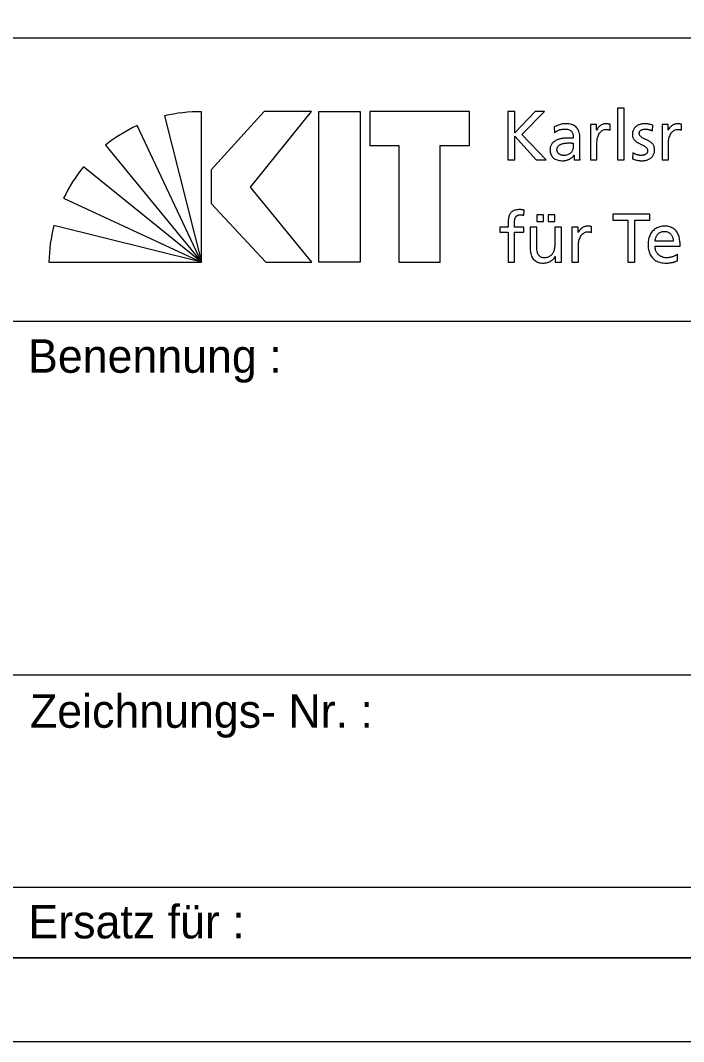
# Model space of a CAD drawing. Extents: x 0 to 594, y 0 to 420.
# Drawn here: x 505.7 to 545.3, y 0 to 61 of the extents above; entities that cross this region are included whole.
import ezdxf

# ---------------------------------------------------------------- set-up
doc = ezdxf.new("R2010")
doc.units = 0
doc.layers.add('90_Plankopf', color=7, linetype='Continuous')

msp = doc.modelspace()

# ---------------------------------------------------------------- linework, layer by layer
at = {"layer": '90_Plankopf'}
for p, q in [((411.12, 59.99), (589, 59.99)), ((411.12, 59.99), (589, 59.99)), ((516.481, 46.586), (516.481, 55.584)), ((534.81, 55.586), (534.81, 52.706)), ((514.275, 55.333), (516.481, 46.586)), ((516.481, 46.586), (512.633, 54.752)), ((537.579, 54.662), (537.6, 54.332)), ((540.926, 54.484), (540.926, 54.831)), ((543.457, 54.439), (543.49, 54.778)), ((545.211, 54.484), (545.211, 54.831)), ((539.118, 53.118), (539.118, 53.989)), ((510.744, 53.585), (516.481, 46.586)), ((538.73, 53.709), (538.73, 53.523)), ((542.297, 53.118), (542.277, 52.772)), ((534.81, 52.706), (535.222, 52.706)), ((536.506, 52.706), (537.108, 52.706)), ((516.481, 46.586), (509.434, 52.286)), ((508.24, 50.413), (516.481, 46.586)), ((535.773, 49.393), (535.79, 49.706)), ((516.481, 46.586), (507.658, 48.788)), ((539.827, 48.365), (539.827, 48.712)), ((544.706, 47.841), (543.616, 47.841)), ((543.616, 47.552), (545.119, 47.552)), ((544.958, 46.673), (544.958, 47.061)), ((507.364, 46.586), (516.481, 46.586)), ((505.001, 43.07), (589, 43.07)), ((505.001, 21.92), (589, 21.92)), ((505.001, 9.23), (589, 9.23)), ((589, 5), (411.12, 5)), ((422.8, 5), (589, 5)), ((422.8, 5), (589, 5))]:
    msp.add_line(p, q, dxfattribs=at)
for points in [[(0, 0), (594, 0), (594, 420), (0, 420)], [(25, 415), (589, 415), (589, 5), (25, 5)], [(523.066, 55.586), (520.236, 55.586), (517.073, 52.099), (517.073, 50.092), (520.338, 46.586), (523.085, 46.586), (519.422, 51.063)], [(525.97, 55.586), (525.97, 46.586), (523.501, 46.586), (523.501, 55.586)], [(526.562, 55.586), (526.562, 53.56), (528.301, 53.56), (528.301, 46.586), (530.771, 46.586), (530.771, 53.56), (532.51, 53.56), (532.51, 55.586)]]:
    msp.add_lwpolyline(points, close=True, dxfattribs=at)
for points in [[(537.108, 52.706), (535.647, 54.224), (537.001, 55.586), (536.452, 55.586), (535.222, 54.319), (535.222, 55.586), (534.81, 55.586)], [(541.381, 52.706), (541.768, 52.706), (541.768, 55.801), (541.381, 55.801), (541.381, 52.706)], [(540.122, 54.484), (540.113, 54.484), (540.113, 54.81), (539.75, 54.81), (539.75, 52.706), (540.138, 52.706), (540.138, 53.663)], [(544.407, 54.484), (544.398, 54.484), (544.398, 54.81), (544.035, 54.81), (544.035, 52.706), (544.423, 52.706), (544.423, 53.663)], [(535.222, 52.706), (535.222, 54.117), (536.506, 52.706)], [(538.763, 52.978), (538.772, 52.978), (538.772, 52.706), (539.135, 52.706)], [(541.99, 46.586), (542.403, 46.586), (542.403, 49.104), (543.298, 49.104), (543.298, 49.467), (541.094, 49.467), (541.094, 49.104), (541.99, 49.104), (541.99, 46.586)], [(534.824, 48.885), (534.824, 48.691), (534.329, 48.691), (534.329, 48.378), (534.824, 48.378), (534.824, 46.586), (535.212, 46.586), (535.212, 48.378), (535.769, 48.378), (535.769, 48.691), (535.212, 48.691), (535.212, 48.918)], [(536.554, 49.426), (536.554, 49.013), (536.942, 49.013), (536.942, 49.426), (536.554, 49.426)], [(537.231, 49.426), (537.231, 49.013), (537.619, 49.013), (537.619, 49.426), (537.231, 49.426)], [(536.542, 47.602), (536.542, 48.691), (536.154, 48.691), (536.154, 47.441)], [(538.015, 46.586), (538.015, 48.691), (537.627, 48.691), (537.627, 47.717)], [(539.022, 48.365), (539.014, 48.365), (539.014, 48.691), (538.651, 48.691), (538.651, 46.586), (539.039, 46.586), (539.039, 47.544)], [(537.631, 46.921), (537.639, 46.921), (537.639, 46.586), (538.015, 46.586)]]:
    msp.add_lwpolyline(points, dxfattribs=at)
for centre, start, end in [((516.449, 46.056), 89.80527, 103.18947), ((516.662, 46.118), 115.01261, 128.3968), ((516.816, 46.263), 140.78977, 154.17397), ((516.891, 46.438), 165.72225, 179.10644)]:
    msp.add_arc(centre, 9.528, start, end, dxfattribs=at)
for points in [[(539.118, 53.989), (539.119, 54.18), (539.091, 54.341), (539.033, 54.47), (538.975, 54.599), (538.884, 54.696), (538.759, 54.762), (538.635, 54.827), (538.472, 54.86), (538.272, 54.86), (538.138, 54.859), (538.014, 54.841), (537.898, 54.804), (537.782, 54.768), (537.676, 54.721), (537.579, 54.662)], [(537.6, 54.332), (537.653, 54.376), (537.713, 54.414), (537.779, 54.446), (537.846, 54.478), (537.916, 54.503), (537.99, 54.52), (538.063, 54.538), (538.137, 54.546), (538.21, 54.546), (538.339, 54.546), (538.441, 54.526), (538.518, 54.485), (538.594, 54.444), (538.649, 54.383), (538.682, 54.302), (538.715, 54.219), (538.731, 54.118), (538.73, 53.997)], [(540.926, 54.831), (540.899, 54.837), (540.873, 54.841), (540.849, 54.846), (540.824, 54.85), (540.798, 54.854), (540.769, 54.856), (540.741, 54.859), (540.708, 54.86), (540.67, 54.86), (540.595, 54.859), (540.523, 54.843), (540.452, 54.811), (540.382, 54.779), (540.318, 54.736), (540.261, 54.679), (540.203, 54.623), (540.157, 54.558), (540.122, 54.484)], [(540.138, 53.663), (540.139, 53.84), (540.163, 53.993), (540.21, 54.121), (540.257, 54.249), (540.323, 54.348), (540.409, 54.416), (540.494, 54.486), (540.595, 54.521), (540.712, 54.521), (540.746, 54.522), (540.78, 54.519), (540.818, 54.514), (540.855, 54.509), (540.891, 54.499), (540.926, 54.484)], [(543.49, 54.778), (543.414, 54.801), (543.337, 54.82), (543.259, 54.836), (543.181, 54.851), (543.097, 54.859), (543.007, 54.86), (542.903, 54.86), (542.805, 54.847), (542.716, 54.82), (542.625, 54.794), (542.547, 54.753), (542.48, 54.7), (542.412, 54.647), (542.359, 54.579), (542.322, 54.498), (542.284, 54.417), (542.265, 54.321), (542.264, 54.212), (542.265, 54.128), (542.282, 54.056), (542.315, 53.994), (542.347, 53.933), (542.391, 53.88), (542.445, 53.834), (542.5, 53.79), (542.559, 53.75), (542.623, 53.715), (542.688, 53.68), (542.753, 53.647), (542.817, 53.617), (542.882, 53.586), (542.942, 53.555), (542.995, 53.522), (543.05, 53.49), (543.093, 53.454), (543.126, 53.413), (543.158, 53.373), (543.176, 53.325), (543.176, 53.271), (543.176, 53.215), (543.163, 53.167), (543.139, 53.128), (543.116, 53.09), (543.084, 53.059), (543.045, 53.035), (543.006, 53.012), (542.963, 52.995), (542.917, 52.985), (542.871, 52.975), (542.825, 52.97), (542.78, 52.97), (542.742, 52.97), (542.695, 52.975), (542.639, 52.986), (542.584, 52.997), (542.526, 53.014), (542.466, 53.036), (542.405, 53.058), (542.35, 53.085), (542.297, 53.118)], [(542.277, 52.772), (542.366, 52.726), (542.46, 52.694), (542.558, 52.678), (542.656, 52.662), (542.755, 52.655), (542.854, 52.656), (542.949, 52.656), (543.04, 52.669), (543.127, 52.695), (543.215, 52.722), (543.293, 52.762), (543.363, 52.816), (543.431, 52.869), (543.487, 52.938), (543.527, 53.02), (543.568, 53.103), (543.588, 53.2), (543.589, 53.312), (543.588, 53.408), (543.571, 53.489), (543.539, 53.556), (543.506, 53.622), (543.462, 53.679), (543.408, 53.726), (543.354, 53.772), (543.295, 53.811), (543.23, 53.845), (543.165, 53.878), (543.101, 53.909), (543.036, 53.937), (542.971, 53.966), (542.912, 53.995), (542.858, 54.026), (542.804, 54.058), (542.76, 54.095), (542.727, 54.136), (542.695, 54.179), (542.678, 54.23), (542.677, 54.291), (542.678, 54.348), (542.696, 54.396), (542.729, 54.434), (542.763, 54.472), (542.808, 54.5), (542.864, 54.519), (542.92, 54.538), (542.982, 54.546), (543.048, 54.546), (543.072, 54.546), (543.102, 54.543), (543.139, 54.538), (543.175, 54.531), (543.213, 54.523), (543.254, 54.513), (543.295, 54.503), (543.333, 54.491), (543.369, 54.478), (543.405, 54.466), (543.434, 54.453), (543.457, 54.439)], [(545.211, 54.831), (545.184, 54.837), (545.158, 54.841), (545.134, 54.846), (545.11, 54.85), (545.083, 54.854), (545.054, 54.856), (545.026, 54.859), (544.993, 54.86), (544.955, 54.86), (544.88, 54.859), (544.808, 54.843), (544.737, 54.811), (544.667, 54.779), (544.603, 54.736), (544.546, 54.679), (544.488, 54.623), (544.442, 54.558), (544.407, 54.484)], [(544.423, 53.663), (544.424, 53.84), (544.448, 53.993), (544.495, 54.121), (544.542, 54.249), (544.608, 54.348), (544.694, 54.416), (544.779, 54.486), (544.88, 54.521), (544.997, 54.521), (545.03, 54.522), (545.065, 54.519), (545.103, 54.514), (545.14, 54.509), (545.175, 54.499), (545.211, 54.484)], [(538.73, 53.997), (538.68, 54), (538.633, 54.002), (538.589, 54.003), (538.546, 54.004), (538.502, 54.005), (538.459, 54.006), (538.415, 54.006), (538.368, 54.006), (538.318, 54.006), (538.237, 54.006), (538.151, 53.999), (538.063, 53.984), (537.973, 53.97), (537.886, 53.947), (537.801, 53.914), (537.715, 53.881), (537.638, 53.838), (537.569, 53.785), (537.499, 53.731), (537.444, 53.665), (537.403, 53.588), (537.362, 53.509), (537.341, 53.418), (537.34, 53.312), (537.341, 53.16), (537.374, 53.035), (537.439, 52.939), (537.504, 52.842), (537.594, 52.77), (537.71, 52.724), (537.825, 52.679), (537.959, 52.656), (538.111, 52.656), (538.2, 52.657), (538.28, 52.668), (538.35, 52.689), (538.421, 52.709), (538.483, 52.736), (538.536, 52.769), (538.59, 52.802), (538.635, 52.837), (538.673, 52.874), (538.71, 52.911), (538.741, 52.945), (538.763, 52.978)], [(538.73, 53.523), (538.73, 53.418), (538.708, 53.323), (538.664, 53.24), (538.62, 53.157), (538.554, 53.092), (538.467, 53.043), (538.38, 52.995), (538.272, 52.97), (538.144, 52.97), (538.1, 52.97), (538.054, 52.978), (538.008, 52.992), (537.963, 53.007), (537.92, 53.028), (537.882, 53.057), (537.843, 53.087), (537.812, 53.123), (537.789, 53.165), (537.765, 53.207), (537.753, 53.257), (537.752, 53.312), (537.754, 53.386), (537.772, 53.448), (537.808, 53.497), (537.844, 53.546), (537.891, 53.586), (537.949, 53.615), (538.007, 53.645), (538.069, 53.667), (538.135, 53.682), (538.201, 53.696), (538.265, 53.706), (538.326, 53.711), (538.387, 53.715), (538.439, 53.717), (538.483, 53.717), (538.524, 53.717), (538.565, 53.715), (538.607, 53.713), (538.648, 53.711), (538.689, 53.709), (538.73, 53.709)], [(539.135, 52.706), (539.132, 52.726), (539.129, 52.753), (539.126, 52.787), (539.125, 52.821), (539.122, 52.865), (539.121, 52.919), (539.119, 52.973), (539.118, 53.039), (539.118, 53.118)], [(535.79, 49.706), (535.751, 49.712), (535.71, 49.719), (535.668, 49.723), (535.625, 49.728), (535.579, 49.731), (535.53, 49.731), (535.388, 49.73), (535.27, 49.71), (535.178, 49.671), (535.086, 49.631), (535.014, 49.574), (534.962, 49.5), (534.91, 49.426), (534.875, 49.337), (534.854, 49.233), (534.833, 49.129), (534.824, 49.014), (534.824, 48.885)], [(535.212, 48.918), (535.212, 48.99), (535.216, 49.056), (535.224, 49.116), (535.232, 49.177), (535.249, 49.23), (535.275, 49.275), (535.3, 49.32), (535.338, 49.355), (535.388, 49.379), (535.439, 49.404), (535.505, 49.417), (535.588, 49.417), (535.621, 49.417), (535.655, 49.415), (535.688, 49.411), (535.722, 49.407), (535.75, 49.401), (535.773, 49.393)], [(539.827, 48.712), (539.8, 48.717), (539.774, 48.722), (539.75, 48.727), (539.725, 48.731), (539.698, 48.734), (539.67, 48.737), (539.642, 48.739), (539.609, 48.74), (539.571, 48.74), (539.496, 48.74), (539.423, 48.724), (539.352, 48.692), (539.282, 48.66), (539.218, 48.616), (539.161, 48.56), (539.104, 48.503), (539.057, 48.439), (539.022, 48.365)], [(539.039, 47.544), (539.039, 47.721), (539.064, 47.873), (539.11, 48.001), (539.158, 48.129), (539.224, 48.228), (539.31, 48.297), (539.395, 48.367), (539.496, 48.401), (539.612, 48.402), (539.646, 48.403), (539.681, 48.4), (539.718, 48.395), (539.756, 48.389), (539.791, 48.379), (539.827, 48.365)], [(545.119, 47.552), (545.119, 47.722), (545.103, 47.88), (545.072, 48.023), (545.041, 48.168), (544.989, 48.293), (544.918, 48.4), (544.846, 48.507), (544.751, 48.591), (544.631, 48.65), (544.512, 48.709), (544.365, 48.74), (544.19, 48.74), (544.041, 48.74), (543.906, 48.714), (543.785, 48.662), (543.665, 48.61), (543.561, 48.537), (543.474, 48.442), (543.387, 48.347), (543.321, 48.235), (543.275, 48.105), (543.228, 47.976), (543.205, 47.833), (543.204, 47.676), (543.204, 47.504), (543.225, 47.348), (543.269, 47.209), (543.312, 47.069), (543.379, 46.95), (543.469, 46.85), (543.558, 46.749), (543.671, 46.672), (543.808, 46.619), (543.945, 46.564), (544.107, 46.538), (544.293, 46.537), (544.408, 46.538), (544.506, 46.545), (544.587, 46.56), (544.667, 46.575), (544.737, 46.593), (544.797, 46.614), (544.855, 46.634), (544.909, 46.654), (544.958, 46.673)], [(543.616, 47.841), (543.623, 47.91), (543.639, 47.978), (543.664, 48.047), (543.688, 48.116), (543.722, 48.179), (543.768, 48.236), (543.812, 48.294), (543.869, 48.339), (543.937, 48.374), (544.006, 48.408), (544.087, 48.426), (544.182, 48.427), (544.266, 48.426), (544.34, 48.411), (544.404, 48.381), (544.47, 48.35), (544.524, 48.309), (544.569, 48.255), (544.614, 48.201), (544.648, 48.139), (544.671, 48.069), (544.694, 47.998), (544.706, 47.922), (544.706, 47.841)], [(537.627, 47.717), (537.627, 47.589), (537.615, 47.471), (537.589, 47.365), (537.564, 47.26), (537.525, 47.169), (537.473, 47.092), (537.421, 47.015), (537.354, 46.956), (537.273, 46.914), (537.193, 46.872), (537.097, 46.851), (536.987, 46.85), (536.875, 46.857), (536.786, 46.889), (536.721, 46.945), (536.656, 47.002), (536.61, 47.084), (536.582, 47.193), (536.554, 47.302), (536.541, 47.438), (536.542, 47.602)], [(536.154, 47.441), (536.154, 47.251), (536.181, 47.09), (536.237, 46.955), (536.293, 46.82), (536.379, 46.717), (536.496, 46.645), (536.612, 46.574), (536.761, 46.538), (536.942, 46.537), (537.04, 46.538), (537.135, 46.553), (537.225, 46.583), (537.315, 46.614), (537.396, 46.658), (537.466, 46.715), (537.537, 46.772), (537.592, 46.841), (537.631, 46.921)], [(544.958, 47.061), (544.933, 47.041), (544.899, 47.019), (544.852, 46.995), (544.806, 46.971), (544.754, 46.948), (544.694, 46.926), (544.634, 46.904), (544.572, 46.886), (544.506, 46.872), (544.44, 46.858), (544.374, 46.851), (544.309, 46.85), (544.217, 46.851), (544.13, 46.868), (544.046, 46.902), (543.964, 46.935), (543.889, 46.983), (543.825, 47.045), (543.761, 47.107), (543.71, 47.181), (543.673, 47.267), (543.636, 47.353), (543.617, 47.448), (543.616, 47.552)]]:
    msp.add_open_spline(points, degree=3, dxfattribs=at)

# ---------------------------------------------------------------- texts
for s, p in [('Benennung :', (506.113, 39.979)), ('Zeichnungs- Nr. :', (506.227, 18.758)), ('Ersatz für :', (506.139, 6.169))]:
    msp.add_text(s, height=2, dxfattribs=at).set_placement(p)

doc.saveas('drawing.dxf')
